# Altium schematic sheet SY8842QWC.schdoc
size 127 x 101 mm
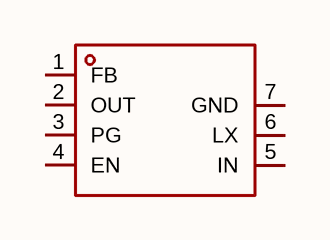
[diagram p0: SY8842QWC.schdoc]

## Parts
U?  sy8842qwc  [QFN-7_L1.5-W1.5-P0.45-BL_SILERGY_SY8842QWC]  (value not drawn)

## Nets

Not connected (* = marked no-connect by the designer): U? 1(FB) 2(OUT) 3(PG) 4(EN) 5(IN) 6(LX) 7(GND)

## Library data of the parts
U? = sy8842qwc: 功能类型:降压型;工作电压:2.6V~5.5V;输出电压:-;输出电流:1.5A;输出类型:可调;; Manufacturer: Silergy(矽力杰); AddInBom: yes; ModelId: f3bb5fc7e8804ea88e1edd7067b238ed; ModelTransform: 59.055,59.055,0,0,0,0,3.936,3.228,0; Function: 降压型; Output Current: 1.5A; Frequency - Switching: 2MHz; Synchronous Rectifier: 是; Number of Outputs: 1; Topology: 降压式; Quiescent Current: 55uA; Switch tube (built-in/external): 内置; Output Type: 可调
